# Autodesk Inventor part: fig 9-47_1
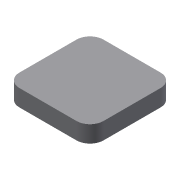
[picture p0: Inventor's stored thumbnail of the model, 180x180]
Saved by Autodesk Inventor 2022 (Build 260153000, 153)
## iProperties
Created: 2013-03
Part Number: fig 9-47_1
Material: Generic
Document SubType Name: Modeling
Designer: CADCIM
Density: 1 g/cm^3
Appearance: Default
Author: CADCIM
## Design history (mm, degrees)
sketch "Sketch1"
  geometry: L1 (-12.5, 12.5)-(12.5, 12.5); L2 (12.5, 12.5)-(12.5, -12.5); L3 (12.5, -12.5)-(-12.5, -12.5); L4 (-12.5, -12.5)-(-12.5, 12.5); 1 further point
  constraints: 8 end point, 2 parallel, 1 horizontal, 1 perpendicular
  dimensions: "d0" = 25 distance of L1.start L1.end; "d2" = 25 distance of L1.end L2.end
extrude "Extrusion1" new body sketch "Sketch1" distance "d3" = 5; taper "d4" = 0 deg
fillet "Fillet1" dims "d5" = 4
body "Solid1"
